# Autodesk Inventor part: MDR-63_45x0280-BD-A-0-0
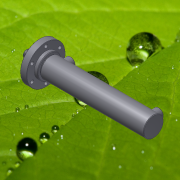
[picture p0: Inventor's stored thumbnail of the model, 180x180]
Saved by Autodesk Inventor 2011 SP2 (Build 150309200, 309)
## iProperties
Created: 2015-10
Part Number: MDR-63_45x0280-BD-A-0-0
Material: Сталь
Document SubType Name: Modeling
Designer: Дорохин
Mass: 17664.9 g
Surface Area: 1563.91 cm^2
Volume: 2250.3 cm^3
Density: 7.85 g/cm^3
Author: Дорохин
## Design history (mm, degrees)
sketch "Эскиз1"
  geometry: L1 (0, 0)-(0, 11.5); L2 (0, 11.5)-(2, 13.5); L3 (2, 13.5)-(22, 13.5); L4 (22, 13.5)-(24, 11.5); L5 (24, 11.5)-(32, 11.5); L6 (32, 11.5)-(32, 20); L7 (32, 20)-(33, 21); L8 (33, 21)-(42, 21); L9 (42, 21)-(43.5, 22.5); L10 (43.5, 22.5)-(48, 22.5); L11 (48, 22.5)-(48, 45); L12 (48, 45)-(50, 45); L13 (50, 45)-(50, 71.5); L14 (50, 71.5)-(51, 72.5); L15 (51, 72.5)-(73, 72.5); L16 (73, 72.5)-(74, 71.5); L17 (74, 71.5)-(74, 44.5); L18 (74, 44.5)-(85, 44.5); L19 (85, 44.5)-(87, 42.5); L20 (87, 42.5)-(87, 35); L21 (87, 35)-(92, 35); L22 (92, 35)-(92, 37.5); L23 (92, 37.5)-(475, 37.5); L24 (477, 35.5)-(477, 0); L25 (477, 0)-(0, 0); L26 (477, 35.5)-(475, 37.5); 1 further point
  constraints: 52 end point, 14 perpendicular, 4 parallel, 2 point on line, 2 vertical
  dimensions: "d0" = 32 distance between parallel lines of L6 L1; "d1" = 48 distance between parallel lines of L1 L11; "d3" = 24 distance between parallel lines of L17 L13; "d4" = 39 distance between parallel lines of L20 L11; "d6" = 429 distance between parallel lines of L24 L11; "d7" = 2 distance between parallel lines of L13 L11; "d8" = 45 deg angle of L15 L14; "d9" = 45 deg angle of L15 L16; "d10" = 75 diameter of L23 L25; "d11" = 89 diameter of L18 L25; "d12" = 145 diameter of L15 L25; "d13" = 143 diameter of L13.end L25 (computed from d12); "d14" = 143 diameter of L16.end L25 (computed from d12); "d15" = 45 deg angle of L18 L19; "d16" = 70 diameter of L21 L25; "d17" = 5 distance between parallel lines of L22 L20; "d18" = 85 diameter of L19.end L25 (computed from d11); "d19" = 90 diameter of L12 L25; "d20" = 45 diameter of L10 L25; "d21" = 45 deg angle of L10 L9; "d22" = 42 diameter of L8 L25; "d23" = 40 diameter of L6.end L25 (computed from d22); "d26" = 10 distance from line of L8.end L6; "d27" = 27 diameter of L3 L25; "d28" = 45 deg angle of L3 L2; "d29" = 23 diameter of L1.end L25; "d30" = 23 diameter of L5 L25; "d31" = 45 deg angle of L3 L4 (derived); "d32" = 10 distance from line of L6 L3.end; "d34" = 2 distance of L24.start point (477, 37.5); "d35" = 2 distance of L23.end point (477, 37.5) (= d34)
revolve "Вращение1" sketch "Эскиз1" stored, may be unused: angle "d33" = 90 deg
sketch "Эскиз2"
  geometry: L1 (-50, 71.5)-(-50, -71.5) reference; L2 (-477, 35.5)-(-477, -35.5) reference; C1 r 18 at (-112, 0); C2 r 18 at (-442, 0); 1 further point
  constraints: 2 centre point
  dimensions: "d36" = 36 diameter of C1 (= d37); "d37" = 36 diameter of C2; "d38" = 0 vertical distance of C2.centre C1.centre; "d39" = 0 vertical distance of C1.centre point (0, 0); "d42" = 62 distance from line of C1.centre L1; "d43" = 35 distance from line of L2 C2.centre
extrude "Выдавливание1" join sketch "Эскиз2" distance "d44" = 54; taper "d45" = 0 deg
hole "Отверстие1" diameter "d48" = 18.631; stored, may be unused: countersink angle "d52" = 90 deg, drill point angle "d54" = 118 deg; dims "d46" = 10, "d47" = 10, "d49" = 20, "d50" = 21, "d51" = 2, "d53" = 25
hole "Отверстие2" diameter "d57" = 18.631; stored, may be unused: countersink angle "d61" = 90 deg, drill point angle "d63" = 118 deg; dims "d55" = 10, "d56" = 10, "d58" = 20, "d59" = 21, "d60" = 2, "d62" = 25
chamfer "Фаска1" distance "d64" = 1; stored, may be unused: second distance "d65" = 2, angle "d66" = 45 deg
sketch "Эскиз3" dims "d68" = 120
  geometry: C1 r 71.5 at (0, 0) reference; C2 r 45 at (0, 0) reference; 2 further points
  constraints: 1 coincident, 1 horizontal alignment, 2 other
  dimensions: "d67" = 0 vertical distance of point (60, 0) C1.centre
hole "Отверстие3" sketch "Эскиз3" at (60, 0) diameter "d69" = 13; stored, may be unused: countersink angle "d73" = 90 deg, drill point angle "d75" = 118 deg; dims "d70" = 25, "d71" = 30, "d72" = 2, "d74" = 30
pattern_circular "Круговой массив1" dims angle "d77" = 360 deg
feature "Резьба1" dims "d79" = 10, "d80" = 0
feature "Резьба2" dims "d81" = 10, "d82" = 0
sketch "Эскиз4"
  geometry: L1 (32, -20)-(32, 20) reference; C1 r 2 at (37, 0); 1 further point
  constraints: 1 centre point
  dimensions: "d83" = 4 diameter of C1; "d84" = 0 vertical distance of C1.centre point (0, 0); "d85" = 5 distance from line of L1 C1.centre
extrude "Выдавливание2" cut sketch "Эскиз4" stored distance "d86" = 90; taper "d87" = 0 deg
node "Твердое тело1"
